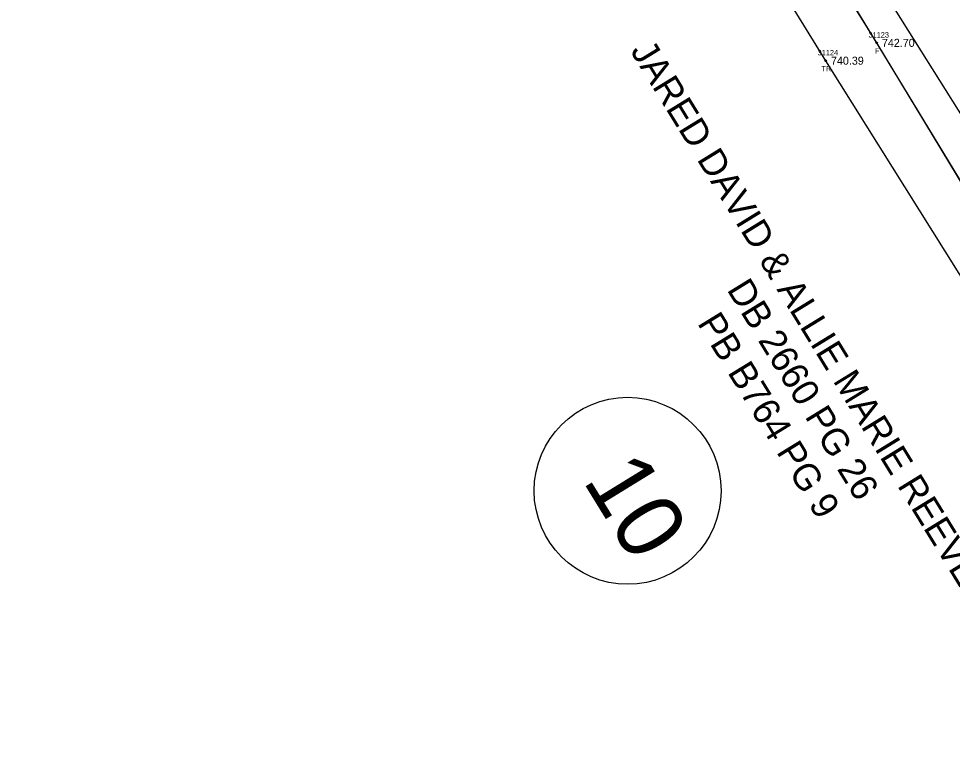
# Model space of a CAD drawing. Extents: x 1375131 to 1378678, y 999028 to 1004053.
# Drawn here: x 1377693.3 to 1377868.1, y 1000661 to 1000797.8 of the extents above; entities that cross this region are included whole.
import ezdxf

# ---------------------------------------------------------------- set-up
doc = ezdxf.new("R2010")
doc.units = 0
for name, color, linetype in [('RD_EX_DV_TX_Prop(Owner ID)', 7, 'Continuous'), ('RD_EX_Fence_Other', 7, 'Continuous'), ('RD_EX_Fence_Other_txCode', 7, 'Continuous'), ('RD_EX_RW', 7, 'Continuous'), ('RD_EX_SU_Elec', 7, 'Continuous'), ('RD_EX_TX_Fence_Other_ELEV', 7, 'Continuous'), ('RD_EX_TX_VEG_ELEV', 7, 'Continuous'), ('RD_EX_VEG', 7, 'Continuous'), ('RD_EX_VEG_txCode', 7, 'Continuous'), ('RD_SMD_Locator', 7, 'Continuous')]:
    doc.layers.add(name, color=color, linetype=linetype)

msp = doc.modelspace()

# ---------------------------------------------------------------- linework, layer by layer
at = {"layer": 'RD_EX_DV_TX_Prop(Owner ID)'}
msp.add_circle((1377807.31, 1000709.38), 17.5, dxfattribs=at)
at = {"layer": 'RD_EX_Fence_Other'}
msp.add_lwpolyline([(1377790.17, 1000897.18), (1377827.38, 1000835.92), (1377853.95, 1000793.25), (1377887.04, 1000738.59), (1377922.52, 1000679.45)], dxfattribs=at)
at = {"layer": 'RD_EX_RW'}
msp.add_line((1377536.4, 1001314.08), (1377927.22, 1000673.01), dxfattribs=at)
at = {"layer": 'RD_EX_SU_Elec'}
msp.add_lwpolyline([(1377798.03, 1000893.79), (1378025.9, 1000531.77), (1378278.5, 1000217.55)], dxfattribs=at)
at = {"layer": 'RD_EX_VEG'}
msp.add_lwpolyline([(1377698.52, 1000917.3), (1377753.14, 1000944.68), (1377782.86, 1000890.37), (1377819.02, 1000831), (1377844.41, 1000789.91), (1377879.22, 1000734.35), (1377912.22, 1000680.73), (1377954.28, 1000611.32), (1377992.95, 1000554.02), (1378022.09, 1000512.01), (1378056.34, 1000459.65), (1378089.87, 1000422.45), (1378122.09, 1000390.03), (1378125.27, 1000369.76), (1378093.99, 1000348.6)], dxfattribs=at)
at = {"layer": 'RD_SMD_Locator'}
for centre in [(1377853.95, 1000793.25), (1377844.41, 1000789.91)]:
    msp.add_circle(centre, 0.15, dxfattribs=at)

# ---------------------------------------------------------------- texts
at = {"layer": 'RD_EX_DV_TX_Prop(Owner ID)'}
for s, height, p in [('JARED DAVID & ALLIE MARIE REEVES', 5, (1377807.73, 1000791.73)), ('DB 2660 PG 26', 5, (1377825.8, 1000747.06)), ('PB B764 PG 9', 5, (1377820.28, 1000740.76)), ('10', 12.5, (1377798.79, 1000711.31))]:
    msp.add_text(s, height=height, rotation=301.5778, dxfattribs=at).set_placement(p)
at = {"layer": 'RD_EX_Fence_Other_txCode'}
for s, p in [('31123', (1377852.43, 1000794.25)), ('F', (1377853.66, 1000791.25))]:
    msp.add_text(s, height=1, dxfattribs=at).set_placement(p)
at = {"layer": 'RD_EX_TX_Fence_Other_ELEV'}
msp.add_text('742.70', height=1.5, dxfattribs=at).set_placement((1377854.95, 1000792.5))
at = {"layer": 'RD_EX_TX_VEG_ELEV'}
msp.add_text('740.39', height=1.5, dxfattribs=at).set_placement((1377845.41, 1000789.16))
at = {"layer": 'RD_EX_VEG_txCode'}
for s, p in [('31124', (1377842.9, 1000790.91)), ('TR', (1377843.62, 1000787.91))]:
    msp.add_text(s, height=1, dxfattribs=at).set_placement(p)

doc.saveas('drawing.dxf')
